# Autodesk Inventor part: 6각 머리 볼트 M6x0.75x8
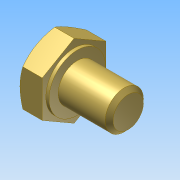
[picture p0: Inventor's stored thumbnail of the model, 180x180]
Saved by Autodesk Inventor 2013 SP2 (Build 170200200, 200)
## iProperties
Created: 2025-10
Part Number: 6각 머리 볼트 M6x0.75x8
Material: Generic
Document SubType Name: Modeling
Designer: a
Density: 1 g/cm^3
Author: a
변환 표준: STEP AP214IS
전처리기: Build: 200, Release: 2013 SP2 Update 6 - Date: Thu 07/17/2014
전송 단위: 밀리미터
불확실성: 0.01
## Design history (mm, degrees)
node "6각 머리 볼트 M6x0.75x81"
body "Solid1"
node "기준1"
